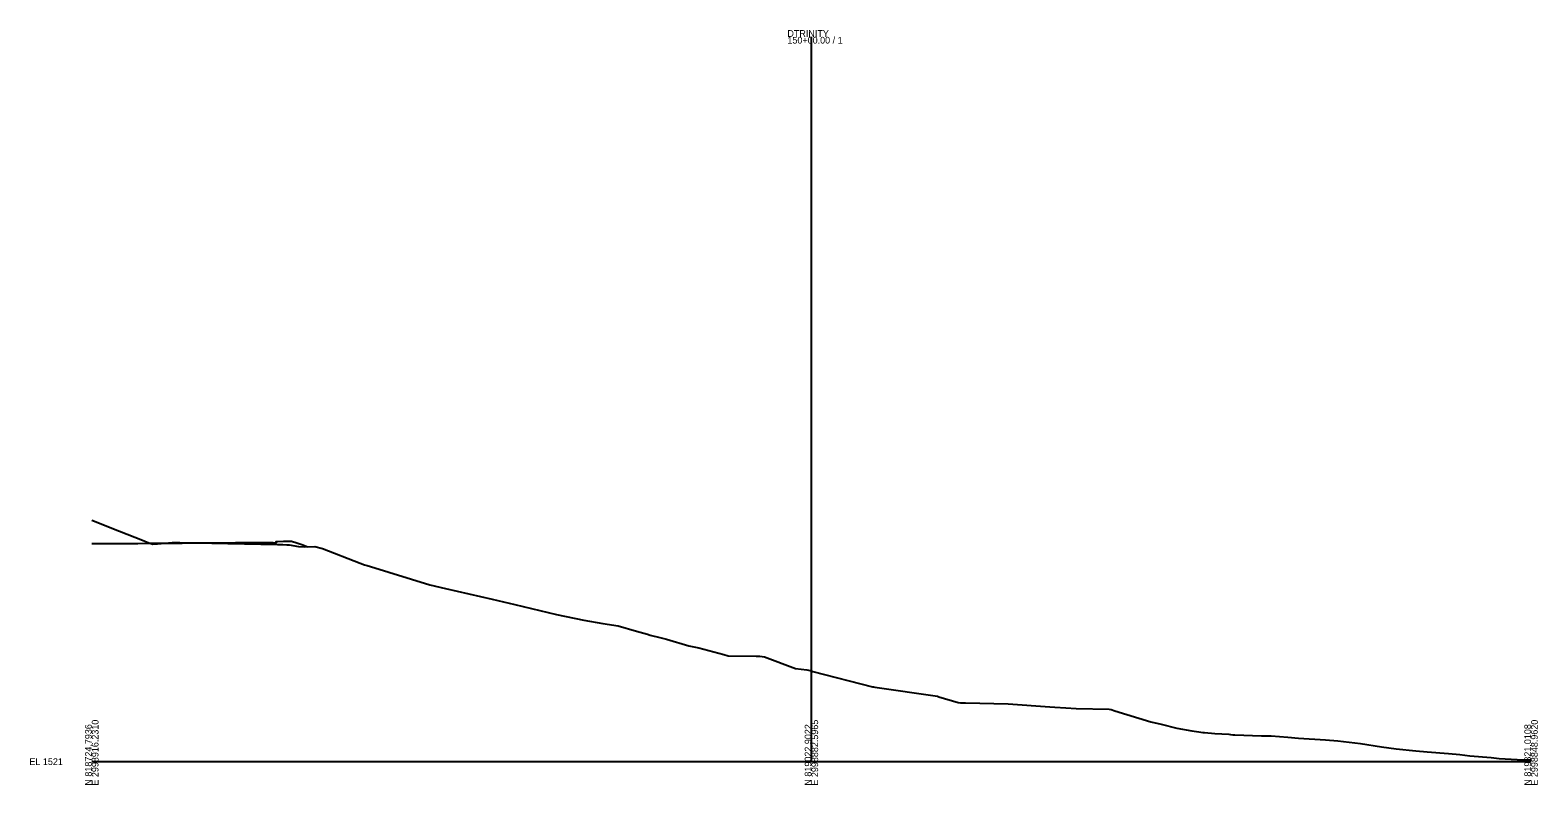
# Model space of a CAD drawing. Extents: x -26 to 603, y -10 to 4805.
# Drawn here: x -26 to 603, y 4490 to 4805 of the extents above; entities that cross this region are included whole.
import ezdxf

# ---------------------------------------------------------------- set-up
doc = ezdxf.new("R2010")
doc.units = 0
for name, color, linetype in [('DESIGN - SHEET - Light Grid', 7, 'Continuous'), ('DESIGN - TYPICAL - Finished Grade and Subgrade', 7, 'Continuous'), ('SURVEY - GROUND - Top of Ground', 7, 'Continuous')]:
    doc.layers.add(name, color=color, linetype=linetype)

msp = doc.modelspace()

# ---------------------------------------------------------------- linework, layer by layer
at = {"layer": 'DESIGN - SHEET - Light Grid'}
for p, q in [((300, 4500), (300, 4802.25)), ((0, 4500), (300, 4500)), ((300, 4500), (600, 4500))]:
    msp.add_line(p, q, dxfattribs=at)
at = {"layer": 'DESIGN - TYPICAL - Finished Grade and Subgrade'}
msp.add_lwpolyline([(0, 4591.01), (1.18, 4591.01), (1.7, 4591.01), (8.7, 4591), (10.4, 4591), (11.95, 4591.01), (16.56, 4591.01), (19.21, 4591.02), (22.83, 4591.04), (24.79, 4591.05), (27.92, 4591.07), (30.55, 4591.08), (33.16, 4591.1), (34.67, 4591.12), (36.76, 4591.14), (37.68, 4591.15), (40.13, 4591.17), (44.42, 4591.22), (45.52, 4591.22), (46.71, 4591.23), (48.46, 4591.24), (48.88, 4591.24), (54.79, 4591.28), (58.47, 4591.3), (59.94, 4591.31), (60.65, 4591.32), (62.76, 4591.33), (68.51, 4591.37), (69.38, 4591.37), (74.35, 4591.4), (75.66, 4591.35), (76.9, 4591.29), (76.9, 4591.77), (77.54, 4591.81), (79.89, 4591.89), (83.28, 4592), (85.43, 4591.22), (87.92, 4590.37), (90.04, 4589.63)], dxfattribs=at)
at = {"layer": 'SURVEY - GROUND - Top of Ground'}
msp.add_lwpolyline([(0, 4600.75), (11.5, 4596.12), (21.09, 4592.39), (23.76, 4591.27), (25.4, 4590.62), (27.34, 4590.82), (33.52, 4591.41), (34.67, 4591.43), (35.01, 4591.42), (36.66, 4591.39), (56.73, 4590.98), (77.45, 4590.56), (79.58, 4590.49), (81.33, 4590.38), (82.22, 4590.45), (86.22, 4589.74), (88.77, 4589.6), (92.99, 4589.68), (96.15, 4588.83), (111.95, 4582.8), (113.66, 4582.01), (114.76, 4581.8), (116.24, 4581.42), (140.96, 4573.71), (147.46, 4572.2), (166.96, 4567.73), (176.42, 4565.58), (193.78, 4561.34), (205.06, 4559.03), (212.98, 4557.62), (219.43, 4556.62), (227.09, 4554.42), (231.63, 4553.19), (232.77, 4552.8), (236.78, 4551.78), (239.63, 4551.03), (248.85, 4548.32), (253.13, 4547.5), (263.55, 4544.72), (265.32, 4544.08), (276.93, 4543.95), (278.49, 4543.92), (280.51, 4543.76), (293.36, 4538.77), (298.15, 4538.22), (300, 4537.79), (300.58, 4537.65), (325.48, 4531.23), (325.83, 4531.17), (326.38, 4531.09), (352.56, 4527.23), (353.07, 4527.04), (361.2, 4524.59), (362.2, 4524.56), (364.17, 4524.48), (382.07, 4524.07), (399.46, 4522.88), (401.5, 4522.74), (406.05, 4522.48), (410.41, 4522.18), (424.1, 4521.88), (424.99, 4521.77), (426.55, 4521.18), (441.55, 4516.59), (445.79, 4515.56), (452.37, 4513.96), (458.64, 4512.83), (461.48, 4512.4), (463.16, 4512.16), (463.88, 4512.09), (468.15, 4511.73), (474.03, 4511.38), (474.77, 4511.31), (475.63, 4511.23), (476.45, 4511.13), (487.62, 4510.75), (490.28, 4510.78), (491.72, 4510.82), (498.65, 4510.15), (503.05, 4509.84), (514.38, 4509.1), (519.42, 4508.64), (528.91, 4507.5), (537.65, 4506.22), (543.78, 4505.35), (552, 4504.55), (556.69, 4504.04), (565.61, 4503.32), (570.27, 4502.96), (574.47, 4502.48), (583.43, 4501.69), (586.78, 4501.28), (594.19, 4500.95), (600, 4500.68)], dxfattribs=at)

# ---------------------------------------------------------------- texts
at = {"layer": 'DESIGN - SHEET - Light Grid'}
for s, p in [('150+00.00 / 1', (290, 4799.45)), ('DTRINITY', (290, 4802.25)), ('EL 1521', (-26, 4498.6))]:
    msp.add_text(s, height=2.8, dxfattribs=at).set_placement(p)
for s, p in [('N 818724.7936', (0, 4490)), ('E 2998916.2310', (2.8, 4490)), ('N 819022.9022', (300, 4490)), ('E 2998882.5965', (302.8, 4490)), ('N 819321.0108', (600, 4490)), ('E 2998848.9620', (602.8, 4490))]:
    msp.add_text(s, height=2.8, rotation=90, dxfattribs=at).set_placement(p)

doc.saveas('drawing.dxf')
